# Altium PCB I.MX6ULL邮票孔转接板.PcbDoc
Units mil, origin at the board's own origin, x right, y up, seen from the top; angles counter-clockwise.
Board outline 1815 x 1660 mil, 2 copper layers (Top Layer, Bottom Layer); 3 components, 118 nets, 240 pads, 181 vias.
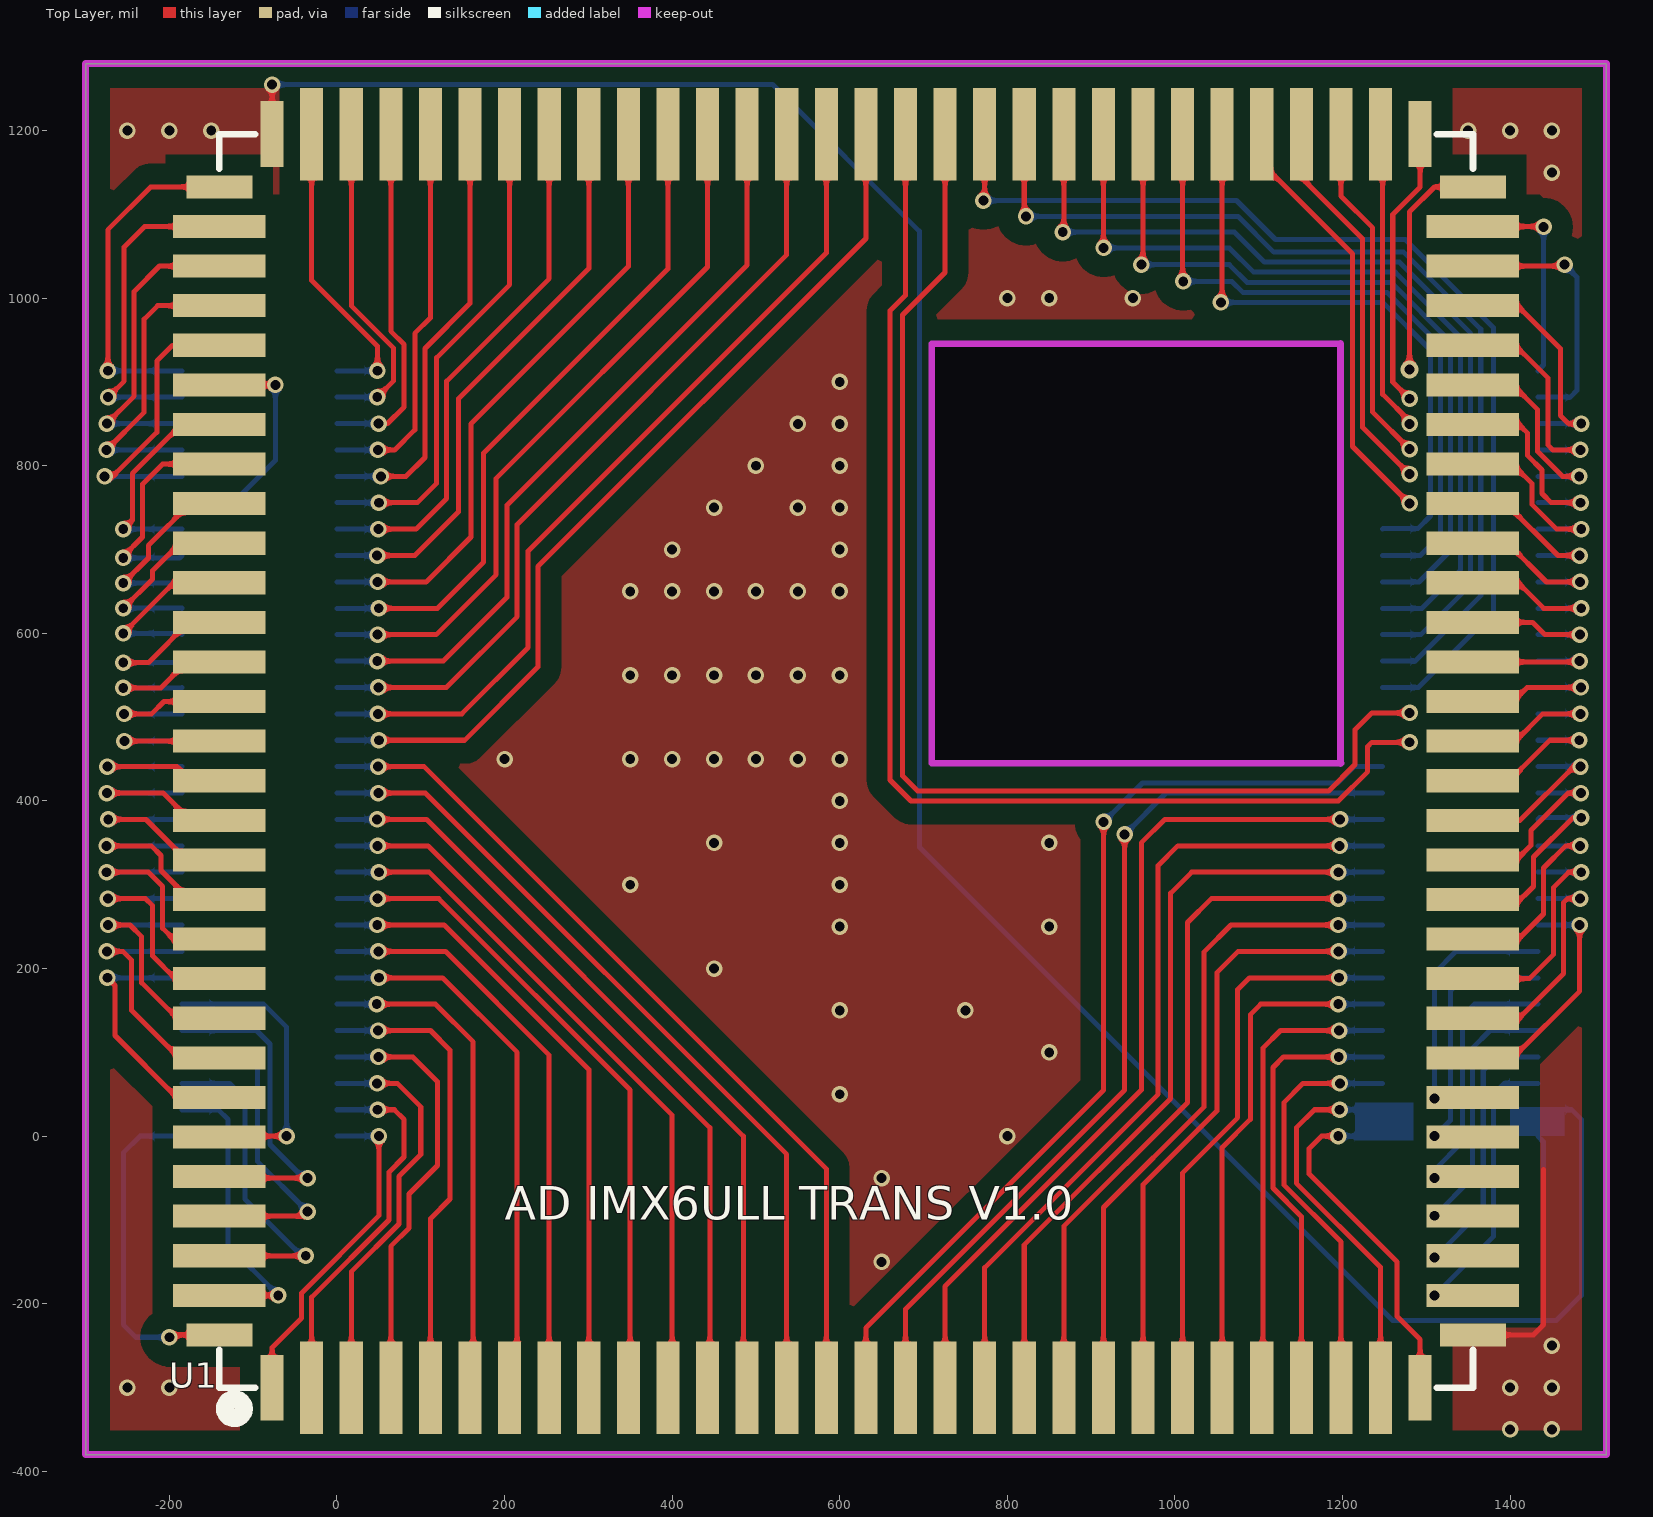
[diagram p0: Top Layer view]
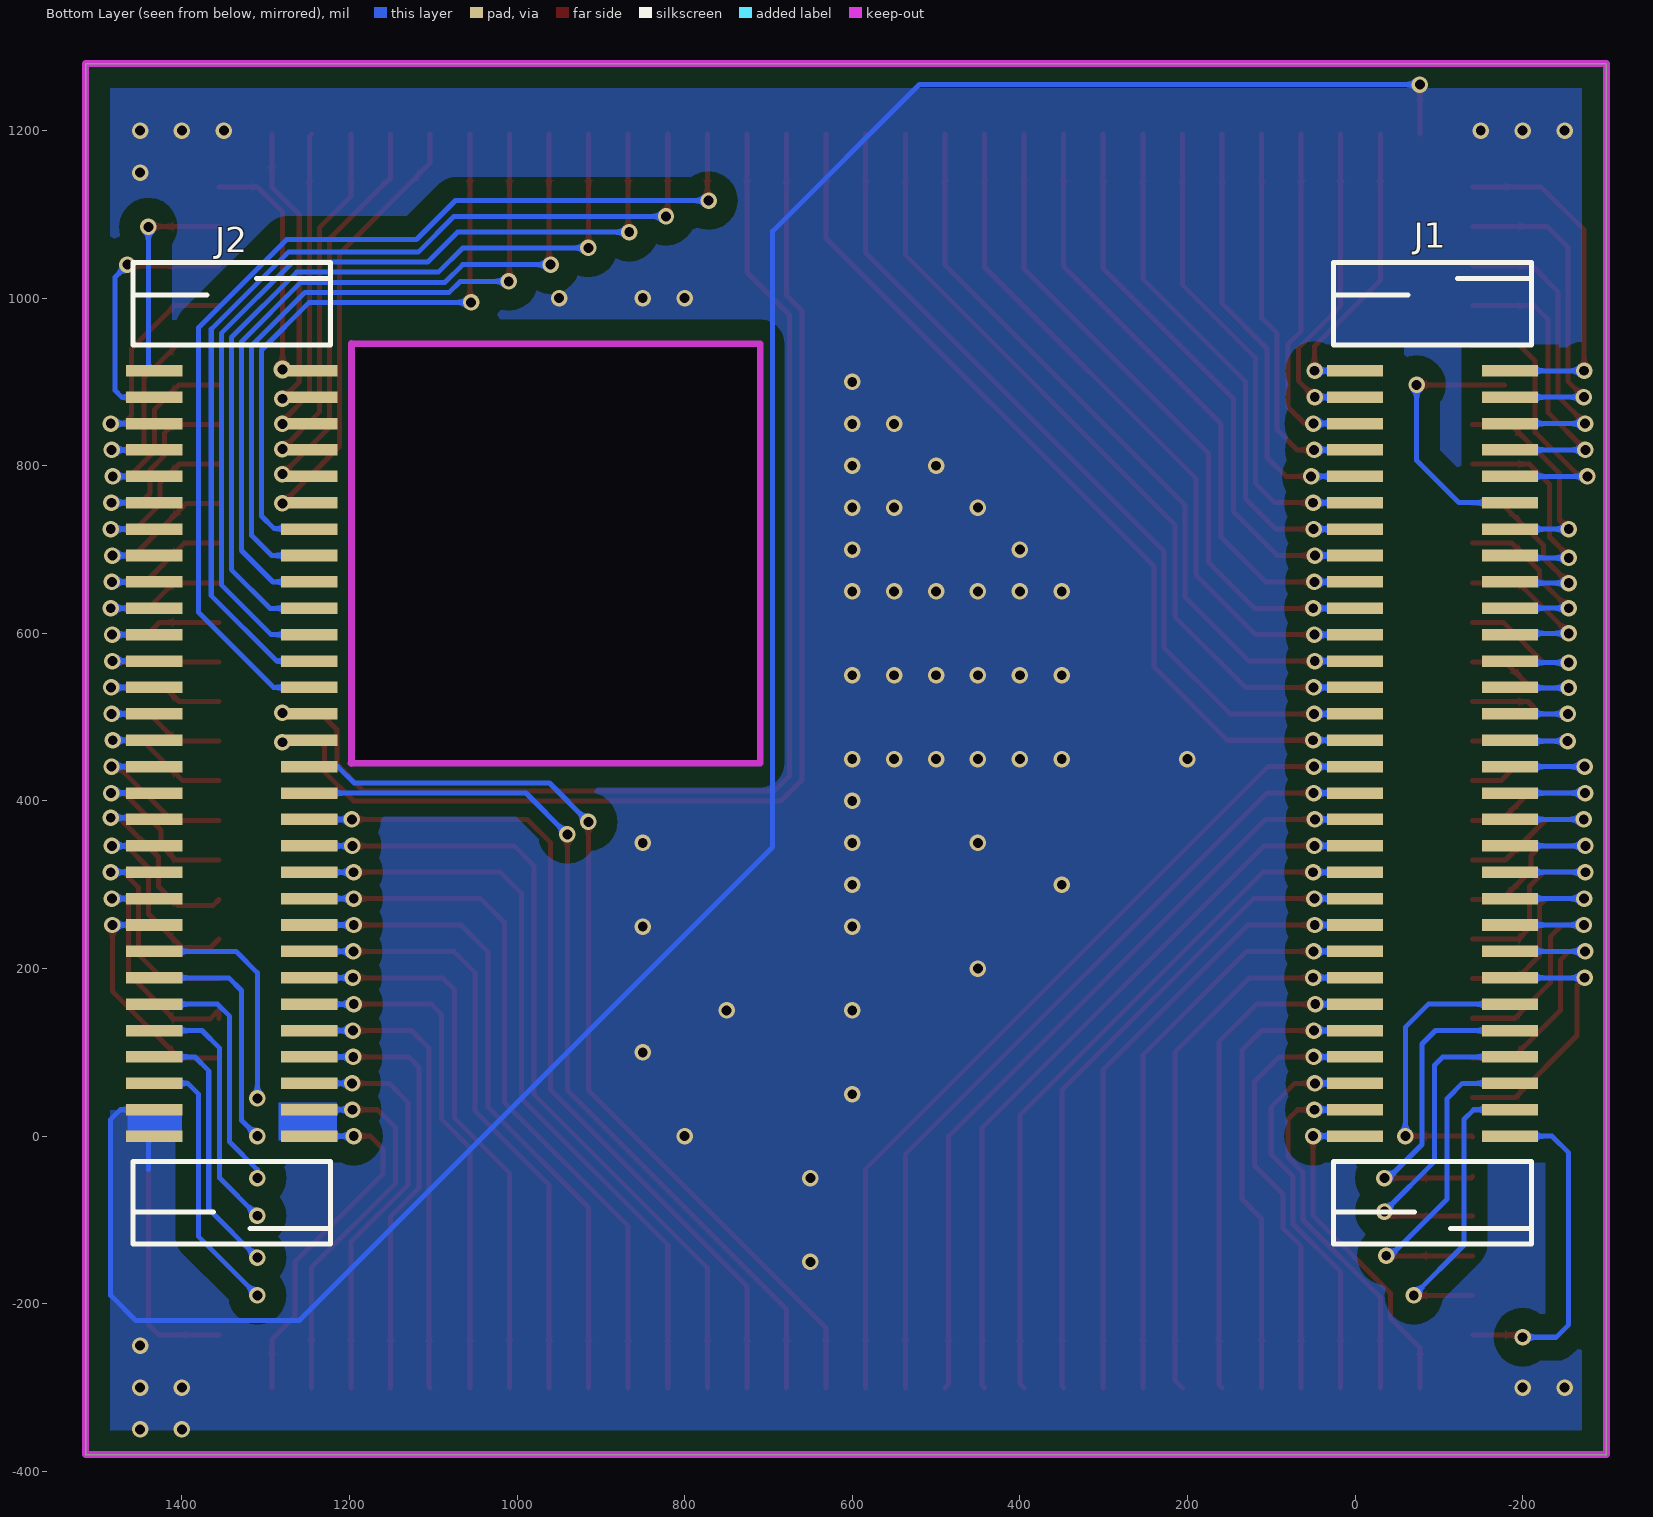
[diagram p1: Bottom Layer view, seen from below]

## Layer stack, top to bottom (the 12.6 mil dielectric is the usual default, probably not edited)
Top Solder: solder mask 0.4, Solder Resist, Dk 3.5
Top Layer: signal copper 1.4
Dielectric 1: dielectric 12.6, FR-4, Dk 4.8
Bottom Layer: signal copper 1.4
Bottom Solder: solder mask 0.4, Solder Resist, Dk 3.5

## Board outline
-300,-380 -300,1280 1515,1280 1515,-380
cut-out: 710,445 710,945.79 1197.6,945.98 1197.6,444.72 1198.19,445

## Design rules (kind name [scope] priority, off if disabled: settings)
Clearance [All] p1: gap=6
ComponentClearance [All] p1 off: gap=10 collisioncheckmode=3 verticalgap=10 showdistances=FALSE
HoleToHoleClearance [All] p1 off: gap=10 allowstackedmicrovias=TRUE
MinimumSolderMaskSliver [All] p1 off: minsoldermaskwidth=10
PlaneClearance [All] p1: clearance=10
PlaneConnect [All] p1: planeconnectstyle=Direct reliefexpansion=20 reliefentries=4 reliefconductorwidth=10 reliefairgap=10
PolygonConnect [All] p1: connectstyle=Direct reliefconductorwidth=10 reliefentries=4 polygonreliefangle="90 Angle" airgapwidth=10
RoutingVias [All] p1: holewidth=28 width=50 viastyle="Through Hole" minholewidth=10 minwidth=11 maxholewidth=900 maxwidth=1000
SilkToSilkClearance [All] p1 off: silktosilkclearance=10
SilkToSolderMaskClearance [IsPad] p1 off: minsilkscreentomaskgap=10 clearancetoexposedcopper=TRUE
SolderMaskExpansion [All] p1: expansion=4
Width [All] p1: maxlimit=1000 minlimit=1 preferedwidth=10
23 further rules are at their usual default settings.

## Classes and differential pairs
component class I.MX6ULL邮票孔转接板: J1 J2

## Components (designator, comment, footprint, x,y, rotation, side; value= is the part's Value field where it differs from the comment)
J1 "3710M060046G3FT01" 3710F060046G3FT01 0,0 r0 bottom locked
J2 "3710M060046G3FT01" 3710F060046G3FT01 1433.07,0 r0 bottom locked
U1 "ATKIMX6ULLCORE-S" ATKIMX6ULLCORE-S -77.4,-300.28 r90 top

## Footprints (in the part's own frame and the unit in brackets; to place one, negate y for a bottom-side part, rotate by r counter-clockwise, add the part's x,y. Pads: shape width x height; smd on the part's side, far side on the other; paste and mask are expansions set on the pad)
3710F060046G3FT01 [mm]
  rect 1.7x0.35 smd: 1(-4.7,0) 2(-4.7,-0.8) 3(-4.7,-1.6) 4(-4.7,-2.4) 5(-4.7,-3.2) 6(-4.7,-4) 7(-4.7,-4.8) 8(-4.7,-5.6) 9(-4.7,-6.4) 10(-4.7,-7.2) 11(-4.7,-8) 12(-4.7,-8.8) 13(-4.7,-9.6) 14(-4.7,-10.4) 15(-4.7,-11.2) 16(-4.7,-12) 17(-4.7,-12.8) 18(-4.7,-13.6) 19(-4.7,-14.4) 20(-4.7,-15.2) 21(-4.7,-16) 22(-4.7,-16.8) 23(-4.7,-17.6) 24(-4.7,-18.4) 25(-4.7,-19.2) 26(-4.7,-20) 27(-4.7,-20.8) 28(-4.7,-21.6) 29(-4.7,-22.4) 30(-4.7,-23.2) 31(0,-23.2) 32(0,-22.4) 33(0,-21.6) 34(0,-20.8) 35(0,-20) 36(0,-19.2) 37(0,-18.4) 38(0,-17.6) 39(0,-16.8) 40(0,-16) 41(0,-15.2) 42(0,-14.4) 43(0,-13.6) 44(0,-12.8) 45(0,-12) 46(0,-11.2) 47(0,-10.4) 48(0,-9.6) 49(0,-8.8) 50(0,-8) 51(0,-7.2) 52(0,-6.4) 53(0,-5.6) 54(0,-4.8) 55(0,-4) 56(0,-3.2) 57(0,-2.4) 58(0,-1.6) 59(0,-0.8) 60(0,0)
  silkscreen extent -5.35,-26.47 0.65,3.27
ATKIMX6ULLCORE-S [mm] "正点原子I.MX6ULL邮票孔核心板"
  rect 2x0.7 smd: 1(0,0) 30(0,-34.8) 61(38,-34.8) 90(38,0)
  rect 2.8x0.7 smd: 2(0,-1.2) 3(0,-2.4) 4(0,-3.6) 5(0,-4.8) 6(0,-6) 7(0,-7.2) 8(0,-8.4) 9(0,-9.6) 10(0,-10.8) 11(0,-12) 12(0,-13.2) 13(0,-14.4) 14(0,-15.6) 15(0,-16.8) 16(0,-18) 17(0,-19.2) 18(0,-20.4) 19(0,-21.6) 20(0,-22.8) 21(0,-24) 22(0,-25.2) 23(0,-26.4) 24(0,-27.6) 25(0,-28.8) 26(0,-30) 27(0,-31.2) 28(0,-32.4) 29(0,-33.6) 62(38,-33.6) 63(38,-32.4) 64(38,-31.2) 65(38,-30) 66(38,-28.8) 67(38,-27.6) 68(38,-26.4) 69(38,-25.2) 70(38,-24) 71(38,-22.8) 72(38,-21.6) 73(38,-20.4) 74(38,-19.2) 75(38,-18) 76(38,-16.8) 77(38,-15.6) 78(38,-14.4) 79(38,-13.2) 80(38,-12) 81(38,-10.8) 82(38,-9.6) 83(38,-8.4) 84(38,-7.2) 85(38,-6) 86(38,-4.8) 87(38,-3.6) 88(38,-2.4) 89(38,-1.2)
  rect 0.7x2 smd: 31(1.6,-36.4) 60(36.4,-36.4) 91(36.4,1.6) 120(1.6,1.6)
  rect 0.7x2.8 smd: 32(2.8,-36.4) 33(4,-36.4) 34(5.2,-36.4) 35(6.4,-36.4) 36(7.6,-36.4) 37(8.8,-36.4) 38(10,-36.4) 39(11.2,-36.4) 40(12.4,-36.4) 41(13.6,-36.4) 42(14.8,-36.4) 43(16,-36.4) 44(17.2,-36.4) 45(18.4,-36.4) 46(19.6,-36.4) 47(20.8,-36.4) 48(22,-36.4) 49(23.2,-36.4) 50(24.4,-36.4) 51(25.6,-36.4) 52(26.8,-36.4) 53(28,-36.4) 54(29.2,-36.4) 55(30.4,-36.4) 56(31.6,-36.4) 57(32.8,-36.4) 58(34,-36.4) 59(35.2,-36.4) 92(35.2,1.6) 93(34,1.6) 94(32.8,1.6) 95(31.6,1.6) 96(30.4,1.6) 97(29.2,1.6) 98(28,1.6) 99(26.8,1.6) 100(25.6,1.6) 101(24.4,1.6) 102(23.2,1.6) 103(22,1.6) 104(20.8,1.6) 105(19.6,1.6) 106(18.4,1.6) 107(17.2,1.6) 108(16,1.6) 109(14.8,1.6) 110(13.6,1.6) 111(12.4,1.6) 112(11.2,1.6) 113(10,1.6) 114(8.8,1.6) 115(7.6,1.6) 116(6.4,1.6) 117(5.2,1.6) 118(4,1.6) 119(2.8,1.6)
  Keep-Out Layer lines w0.203: 18.923,-32.385 31.65,-32.385 ; 31.655,-32.385 31.65,-20 18.93,-20 18.93,-32.4
  silkscreen extent -0.92,-36.4 38,1.6

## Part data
J1 J2: library part 3710F, "3710F060046G3FT01"
U1: "正点原子I.MX6ULL邮票孔核心板"

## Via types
v1: diameter 19.68, hole 11.81, Top Layer to Bottom Layer, 180 vias
v2: diameter 21.65, hole 11.81, Top Layer to Bottom Layer, 1 vias

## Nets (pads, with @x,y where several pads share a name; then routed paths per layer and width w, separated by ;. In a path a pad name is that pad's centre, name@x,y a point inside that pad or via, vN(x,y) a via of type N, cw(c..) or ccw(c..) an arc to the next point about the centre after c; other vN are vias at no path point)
6D_INT: J2.22 U1.68 | length 909.3
  Top Layer w6: v1(960,1040) 961.97,1041.97 U1.68
  Bottom Layer w6: v1(960,1040) 1065,1040 1086,1019 1258.12,1019 1329,948.12 1329,699 1291.42,661.42 J2.22
AP_INT: J2.49 U1.41 | length 265.1
  Top Layer w6: U1.41 1365.83,225 1400,225 1440,265 1440,320 1466.46,346.46 v1(1483.54,346.46)
  Bottom Layer w6: J2.49 v1(1483.54,346.46)
AUD_INT: J2.3 U1.28 | length 496.1
  Top Layer w6: v1(1197.01,62.99) 1152.99,62.99 1130,40 1130,-58.03 1198.19,-126.22 U1.28
  Bottom Layer w6: v1(1197.01,62.99) J2.3
BEEP: J2.5 U1.26 | length 557.5
  Top Layer w6: U1.26 1105,-298.98 1105,105 1125.98,125.98 v1(1195.98,125.98)
  Bottom Layer w6: v1(1195.98,125.98) J2.5
BLT_PWM: J2.16 U1.74 | length 1455.4
  Top Layer w6: U1.74 678.5,1003.5 660,985 660,425 685,400 1195,400 1230,435 1230,465 1235,470 v1(1280,470)
BOOT_MODE0: J2.7 U1.24 | length 681.3
  Top Layer w6: U1.24 1009.21,-43.82 1075,21.97 1075,175 1088.98,188.98 v1(1196.02,188.98)
  Bottom Layer w6: v1(1196.02,188.98) J2.7
BOOT_MODE1: J2.8 U1.23 | length 740.3
  Top Layer w6: U1.23 961.97,-58.03 1050,30 1050,195 1075.47,220.47 v1(1195.47,220.47)
  Bottom Layer w6: v1(1195.47,220.47) J2.8
CAN1_RX: J2.35 U1.55 | length 251
  Top Layer w6: U1.55 1403.43,896.57 1433,867 1433,817 1462.6,787.4 v1(1482.6,787.4)
  Bottom Layer w6: J2.35 v1(1482.6,787.4)
CAN1_TX: J2.36 U1.54 | length 250.4
  Top Layer w6: U1.54 1410.67,849.33 1421,839 1421,812.03 1438,795.03 1438,767 1449.09,755.91 v1(1484.09,755.91)
  Bottom Layer w6: J2.36 v1(1484.09,755.91)
CSI_DATA0: J1.56 U1.5 | length 557.2
  Top Layer w6: v1(49.02,125.98) 111.57,125.98 135,102.56 135,-75 111.57,-98.43 U1.5
  Bottom Layer w6: J1.56 v1(49.02,125.98)
CSI_DATA1: J1.57 U1.4 | length 520.5
  Top Layer w6: v1(49.49,94.49) 90.51,94.49 120,65 120,-35 86,-69 86,-109.91 64.33,-131.58 U1.4
  Bottom Layer w6: J1.57 v1(49.49,94.49)
CSI_DATA2: J1.3 U1.118 | length 406.6
  Top Layer w6: U1.118 v1(-37.2,-142.8)
  Bottom Layer w6: J1.3 -127.99,62.99 -110,45 -110,-75 -42.2,-142.8 v1(-37.2,-142.8)
CSI_DATA3: J1.59 U1.2 | length 450.7
  Top Layer w6: U1.2 -30.16,-192.13 62,-99.97 62,-43 80,-25 80,20 68.5,31.5 v1(48.5,31.5)
  Bottom Layer w6: J1.59 v1(48.5,31.5)
CSI_DATA4: J1.55 U1.6 | length 595.4
  Top Layer w6: v1(47.52,157.48) 117.52,157.48 162.52,112.48 162.52,-296.57 U1.6
  Bottom Layer w6: J1.55 v1(47.52,157.48)
CSI_DATA5: J1.6 U1.115 | length 347.3
  Top Layer w6: U1.115 -139.33,0 v1(-60,0)
  Bottom Layer w6: J1.6 -87.48,157.48 -60,130 v1(-60,0)
CSI_DATA6: J1.4 U1.117 | length 398
  Top Layer w6: U1.117 -40.55,-95.55 v1(-35,-90)
  Bottom Layer w6: J1.4 -104.49,94.49 -95,85 -95,-30 v1@-37.5,-87.5
CSI_DATA7: J1.58 U1.3 | length 481.2
  Top Layer w6: U1.3 17.09,-161.85 74,-104.94 74,-47.97 100,-21.97 100,35 72.01,62.99 v1(47.99,62.99)
  Bottom Layer w6: J1.58 v1(47.99,62.99)
CSI_HSYNC: J1.1 U1.120 | length 405.2
  Top Layer w6: v1(-200,-240) -197.28,-237.28 U1.120
  Bottom Layer w6: v1(-200,-240) -240,-240 -255,-225 -255,-20 -235,0 J1.1
CSI_MCLK: J1.2 U1.119 | length 365.1
  Top Layer w6: U1.119 v1(-70,-190.04)
  Bottom Layer w6: J1.2 -141.5,31.5 -130,20 -130,-130 v1(-70,-190.04)
CSI_PIXCLK: J1.5 U1.116 | length 399.3
  Top Layer w6: U1.116 -138.7,-50 v1(-35,-50)
  Bottom Layer w6: J1.5 -95.98,125.98 -80,110 -80,-10 -40,-50 v1(-35,-50)
CSI_PWDN: J2.14 U1.17 | length 1097.1
  Top Layer w6: U1.17 678.5,-206.5 940,55 v1(940,360)
  Bottom Layer w6: v1(940,360) 989.45,409.45 J2.14
CSI_RESET: J2.13 U1.18 | length 1051.2
  Top Layer w6: U1.18 725.75,-179.25 960,55 960,350 987.95,377.95 v1(1197.05,377.95) v1@1197.05,373.69
  Bottom Layer w6: v1(1197.05,377.95) J2.13
CSI_VSYNC: J1.60 U1.1 | length 403
  Top Layer w6: U1.1 -77.4,-252.4 -42.16,-217.16 -42.16,-187.16 50,-95 v1(50,0)
  Bottom Layer w6: J1.60 v1(50,0)
CT_INT: J2.15 U1.16 | length 1153.2
  Top Layer w6: U1.16 631.26,-228.74 915,55 v1(915,375)
  Bottom Layer w6: v1(915,375) 961.45,421.45 1194.48,421.45 1213.97,440.94 J2.15
CT_RST: J1.48 U1.13 | length 943.7
  Top Layer w6: v1(47.95,377.95) 107.05,377.95 485,0 485,-295.75 U1.13
  Bottom Layer w6: J1.48 v1(47.95,377.95)
DC5V: J2.1 J2.2 U1.29 U1.30 | length 898.3
  Top Layer w6: v1(1195,0) 1175,0 1160,-15 1160,-45 1265,-150 1265,-215 1292.68,-242.68 U1.30 ; v1(1196.5,31.5) 1166.5,31.5 1145,10 1145,-56.06 1245.43,-156.49 U1.29
  Bottom Layer w6: v1(1195,0) J2.1 ; v1(1196.5,31.5) J2.2
ECSPI3_MISO: J2.40 U1.50 | length 193.9
  Top Layer w6: U1.50 1409.65,660.35 1440.08,629.92 v1(1485,629.92)
  Bottom Layer w6: J2.40 v1(1485,629.92)
ECSPI3_MOSI: J2.39 U1.51 | length 197.6
  Top Layer w6: U1.51 1397.4,707.6 1443.58,661.42 v1(1483.58,661.42)
  Bottom Layer w6: J2.39 v1(1483.58,661.42)
ECSPI3_SCLK: J2.41 U1.49 | length 184.2
  Top Layer w6: U1.49 1426.89,613.11 1441.57,598.43 v1(1483.43,598.43)
  Bottom Layer w6: J2.41 v1(1483.43,598.43)
ECSPI3_SS0: J2.42 U1.48 | length 177.8
  Top Layer w6: U1.48 1482.01,565.87 v1(1483.07,566.93)
  Bottom Layer w6: J2.42 v1(1483.07,566.93)
ENET1_CRS_DV: J2.25 U1.65 | length 513.8
  Top Layer w6: U1.65 1103.7,1161.3 1212,1053 1212,823 v1(1280,755)
ENET1_INT: J2.11 U1.20 | length 926
  Top Layer w6: U1.20 820.24,-129.76 995,45 995,290 1019.96,314.96 v1(1195.04,314.96)
  Bottom Layer w6: v1(1195.04,314.96) J2.11
ENET1_RST: J2.10 U1.21 | length 861.2
  Top Layer w6: U1.21 867.48,-107.52 1015,40 1015,255 1043.46,283.46 v1(1195,283.46)
  Bottom Layer w6: v1(1195,283.46) J2.10
ENET1_RXD0: J2.26 U1.64 | length 459.2
  Top Layer w6: U1.64 1150.94,1144.06 1224,1071 1224,846 v1(1280,790)
ENET1_RXD1: J2.24 U1.66 | length 736.5
  Top Layer w6: v1(1055,995) 1056.46,996.46 U1.66
  Bottom Layer w6: v1(1055,995) 1248.18,995 1305,938.18 1305,740 1290,725 1248.62,725 J2.24
ENET1_RXER: J2.30 U1.60 | length 276
  Top Layer w6: v2(1280,915) 1280,1103.03 1309.77,1132.8 U1.60
ENET1_TX_CLK: J2.29 U1.61 | length 337.6
  Top Layer w6: v1(1280,880) 1260,900 1260,1100 1292.68,1132.68 U1.61
ENET1_TXD0: J2.23 U1.67 | length 820
  Top Layer w6: U1.67 1009.21,1020.79 v1(1010,1020)
  Bottom Layer w6: v1(1010,1020) 1068.03,1020 1081.03,1007 1253.15,1007 1317,943.15 1317,717 1292.91,692.91 J2.23
ENET1_TXD1: J2.28 U1.62 | length 360.1
  Top Layer w6: U1.62 1248,1193.22 1248,885.35 1280,853.35 v1(1280,850)
ENET1_TXEN: J2.27 U1.63 | length 409.7
  Top Layer w6: U1.63 1198.19,1121.81 1236,1084 1236,864 v1(1280,820)
ENET2_CRS_DV: J1.33 U1.87 | length 420.4
  Top Layer w6: v1(49.61,850.39) 60.39,850.39 80,870 80,945 64.33,960.67 U1.87
  Bottom Layer w6: J1.33 v1(49.61,850.39)
ENET2_INT: J1.39 U1.81 | length 740.8
  Top Layer w6: v1(48.58,661.42) 106.42,661.42 160,715 160,850 347.8,1037.8 U1.81
  Bottom Layer w6: J1.39 v1(48.58,661.42)
ENET2_RST: J2.9 U1.22 | length 796.4
  Top Layer w6: U1.22 914.72,-85.28 1035,35 1035,220 1066.97,251.97 v1(1195,251.97)
  Bottom Layer w6: v1(1195,251.97) J2.9
ENET2_RXD0: J1.38 U1.82 | length 681.8
  Top Layer w6: v1(47.91,692.91) 92.91,692.91 145,745 145,880 300.55,1035.55 U1.82
  Bottom Layer w6: J1.38 v1(47.91,692.91)
ENET2_RXD1: J1.37 U1.83 | length 631.6
  Top Layer w6: v1(49.41,724.41) 94.41,724.41 131,761 131,901 253.31,1023.31 U1.83
  Bottom Layer w6: J1.37 v1(49.41,724.41)
ENET2_RXER: J1.34 U1.86 | length 463.5
  Top Layer w6: v1(48.9,818.9) 68.9,818.9 93,843 93,958 111.57,976.57 U1.86
  Bottom Layer w6: J1.34 v1(48.9,818.9)
ENET2_TX_CLK: J1.31 U1.89 | length 363.3
  Top Layer w6: U1.89 -30.16,1021.22 48.39,942.67 v1(48.39,913.39)
  Bottom Layer w6: J1.31 v1(48.39,913.39)
ENET2_TXD0: J1.36 U1.84 | length 581.4
  Top Layer w6: v1(50,755.91) 95.91,755.91 119,779 119,929 206.06,1016.06 U1.84
  Bottom Layer w6: J1.36 v1(50,755.91)
ENET2_TXD1: J1.35 U1.85 | length 522.4
  Top Layer w6: v1(52.4,787.4) 82.4,787.4 105,810 105,940 158.82,993.82 U1.85
  Bottom Layer w6: J1.35 v1(52.4,787.4)
ENET2_TXEN: J1.32 U1.88 | length 390.7
  Top Layer w6: U1.88 17.09,990.94 67.23,940.8 67.23,901.01 v1(48.11,881.89)
  Bottom Layer w6: J1.32 v1(48.11,881.89)
GND: J2.59 J2.60 U1.31 U1.90 | length 3259.5
  Top Layer w6: U1.90 v1(-77.4,1255) ; U1.31 1427.72,-237.28 1440,-225 1440,-40
  Bottom Layer w6: v1(-77.4,1255) 520,1255 695,1080 695,345 1260,-220 1455,-220 1485,-190 1485,20 1473.5,31.5 J2.59 ; J2.60 1440,-6.93 1440,-40
  other v1: 1400,-350 1450,-350 -250,-300 -200,-300 1400,-300 1450,-300 1450,-250 650,-150 650,-50 800,0 600,50 850,100 600,150 750,150 450,200 600,250 850,250 350,300 600,300 450,350 600,350 850,350 600,400 200,450 350,450 400,450 450,450 500,450 550,450 600,450 350,550 400,550 450,550 500,550 550,550 600,550 350,650 400,650 450,650 500,650 550,650 600,650 400,700 600,700 450,750 550,750 600,750 500,800 600,800 550,850 600,850 600,900 800,1000 850,1000 950,1000 1450,1150 -250,1200 -200,1200 -150,1200 1350,1200 1400,1200 1450,1200
GPIO_0: J2.51 U1.39 | length 301.8
  Top Layer w6: U1.39 1355.67,150.67 1366.34,140 1410,140 1464,194 1464,279 1468.46,283.46 v1(1483.46,283.46)
  Bottom Layer w6: J2.51 v1(1483.46,283.46)
GPIO_3: J2.47 U1.43 | length 223.8
  Top Layer w6: U1.43 1407.68,329.65 1425,346.97 1425,365 1469.45,409.45 v1(1484.45,409.45)
  Bottom Layer w6: J2.47 v1(1484.45,409.45)
GPIO_5: J1.47 U1.14 | length 993.9
  Top Layer w6: v1(49.45,409.45) 105.55,409.45 536.77,-21.77 U1.14
  Bottom Layer w6: J1.47 v1(49.45,409.45)
GPIO_6: J2.44 U1.46 | length 192.6
  Top Layer w6: U1.46 1406.38,471.38 1438.94,503.94 v1(1483.94,503.94)
  Bottom Layer w6: J2.44 v1(1483.94,503.94)
GPIO_7: J2.45 U1.45 | length 196.4
  Top Layer w6: U1.45 1399.13,424.13 1447.44,472.44 v1(1482.56,472.44)
  Bottom Layer w6: J2.45 v1(1482.56,472.44)
I2C1_SCL: J2.33 U1.57 | length 286.4
  Top Layer w6: U1.57 1408.94,991.06 1460,940 1460,860 1469.61,850.39 v1(1485,850.39)
  Bottom Layer w6: J2.33 v1(1485,850.39)
I2C1_SDA: J2.34 U1.56 | length 277.7
  Top Layer w6: U1.56 1406.18,943.82 1445,905 1445,825 1451.1,818.9 v1(1483.9,818.9)
  Bottom Layer w6: J2.34 v1(1483.9,818.9)
I2C2_SCL: J2.31 U1.59 | length 259
  Top Layer w6: U1.59 1439.45,1085.55 v1(1440,1085)
  Bottom Layer w6: J2.31 1440,920.31 v1(1440,1085)
I2C2_SDA: J2.32 U1.58 | length 316.5
  Top Layer w6: U1.58 1463.31,1038.31 v1(1465,1040)
  Bottom Layer w6: J2.32 1471.89,881.89 1480,890 1480,1025 v1(1465,1040)
JTAG_NTRST: J2.21 U1.69 | length 995.3
  Top Layer w6: U1.69 914.72,1060.28 v1(915,1060)
  Bottom Layer w6: v1(915,1060) 1065,1060 1094,1031 1263.09,1031 1341,953.09 1341,676 1294.92,629.92 J2.21
JTAG_TCK: J2.19 U1.71 | length 1164.8
  Top Layer w6: U1.71 820.24,1099.76 v1(822.32,1097.69)
  Bottom Layer w6: v1(822.32,1097.69) 1075.34,1097.69 1118.03,1055 1273.03,1055 1365,963.03 1365,645 1286.93,566.93 J2.19
JTAG_TDI: J2.17 U1.73 | length 1462.1
  Top Layer w6: U1.73 725.75,1030.75 675,980 675,430 693,412 1183.57,412 1215,443.43 1215,485 1235,505 v1(1280,505)
JTAG_TDO: J2.18 U1.72 | length 1260.2
  Top Layer w6: v1(771.53,1116.53) 772.99,1117.99 U1.72
  Bottom Layer w6: v1(771.53,1116.53) 1073.47,1116.53 1120,1070 1275,1070 1380,965 1380,625 1290.43,535.43 J2.18
JTAG_TMS: J2.20 U1.70 | length 1084.1
  Top Layer w6: v1(866.16,1078.84) 867.48,1080.17 U1.70
  Bottom Layer w6: v1(866.16,1078.84) 1071.16,1078.84 1107,1043 1268.06,1043 1353,958.06 1353,658 1293.43,598.43 J2.20
KEY0: J2.48 U1.42 | length 249.2
  Top Layer w6: U1.42 1363.07,275 1405,275 1428,298 1428,333 1475,380 v1(1485,380)
  Bottom Layer w6: J2.48 1435.12,380 v1(1485,380)
LCD_DATA0: J1.7 U1.114 | length 316.8
  Top Layer w6: v1(-273.98,188.98) -265,180 -265,120 -191.18,46.18 U1.114
  Bottom Layer w6: v1(-273.98,188.98) J1.7
LCD_DATA1: J1.8 U1.113 | length 311.4
  Top Layer w6: v1(-274.53,220.47) -255.47,220.47 -245,210 -245,150 -188.43,93.43 U1.113
  Bottom Layer w6: v1(-274.53,220.47) J1.8
LCD_DATA2: J1.9 U1.112 | length 298.9
  Top Layer w6: v1(-273.03,251.97) -246.97,251.97 -233,238 -233,183 -190.67,140.67 U1.112
  Bottom Layer w6: v1(-273.03,251.97) J1.9
LCD_DATA3: J1.10 U1.111 | length 296.2
  Top Layer w6: v1(-273.46,283.46) -228.46,283.46 -220,275 -220,215 -192.91,187.91 U1.111
  Bottom Layer w6: v1(-273.46,283.46) J1.10
LCD_DATA4: J1.11 U1.110 | length 286.8
  Top Layer w6: v1(-274.96,314.96) -224.96,314.96 -208,298 -208,248 -195.16,235.16 U1.110
  Bottom Layer w6: v1(-274.96,314.96) J1.11
LCD_DATA5: J1.12 U1.109 | length 261.7
  Top Layer w6: v1(-275,346.46) -221.46,346.46 -210,335 -210,316.97 -175.43,282.4 U1.109
  Bottom Layer w6: v1(-275,346.46) J1.12
LCD_DATA6: J1.13 U1.108 | length 240.5
  Top Layer w6: v1(-272.95,377.95) -227.95,377.95 -179.65,329.65 U1.108
  Bottom Layer w6: v1(-272.95,377.95) J1.13
LCD_DATA7: J1.14 U1.107 | length 237
  Top Layer w6: v1(-274.45,409.45) -274.39,409.51 -207.4,409.51 -174.78,376.89 U1.107
  Bottom Layer w6: v1(-274.45,409.45) J1.14
LCD_DATA8: J1.15 U1.106 | length 229.6
  Top Layer w6: v1(-274.06,440.94) -190.94,440.94 -174.13,424.13 U1.106
  Bottom Layer w6: v1(-274.06,440.94) J1.15
LCD_DATA9: J1.16 U1.105 | length 182.3
  Top Layer w6: v1(-253.62,471.38) U1.105
  Bottom Layer w6: v1(-253.62,471.38) -186.1,471.38 J1.16
LCD_DATA10: J1.17 U1.104 | length 190
  Top Layer w6: v1(-253.94,503.94) -221.06,503.94 -206.38,518.62 U1.104
  Bottom Layer w6: v1(-253.94,503.94) J1.17 J1.17@-186.1,505
LCD_DATA11: J1.18 U1.103 | length 197.5
  Top Layer w6: v1(-255,535) -210,535 -179.13,565.87 U1.103
  Bottom Layer w6: v1(-255,535) -185.47,535 J1.18
LCD_DATA12: J1.19 U1.102 | length 205.3
  Top Layer w6: v1(-255,565) -225,565 -176.89,613.11 U1.102
  Bottom Layer w6: v1(-255,565) -186.97,565 J1.19
LCD_DATA13: J1.20 U1.101 | length 210.2
  Top Layer w6: v1(-255,600) -194.65,660.35 U1.101
  Bottom Layer w6: v1(-255,600) -186.61,600 J1.20
LCD_DATA14: J1.21 U1.100 | length 222.6
  Top Layer w6: v1(-255,630) -220,665 -220,675 -187.4,707.6 U1.100
  Bottom Layer w6: v1(-255,630) -185.12,630 J1.21
LCD_DATA15: J1.22 U1.99 | length 233.2
  Top Layer w6: v1(-255,660) -225,690 -225,705 -175.16,754.84 U1.99
  Bottom Layer w6: v1(-255,660) -186.46,660 J1.22
LCD_DATA16: J1.23 U1.98 | length 270.3
  Top Layer w6: v1(-255,690) -255,691.97 -232,714.97 -232,778 -207.91,802.09 U1.98
  Bottom Layer w6: v1(-255,690) -187.95,690 J1.23
LCD_DATA17: J1.24 U1.97 | length 268.9
  Top Layer w6: v1(-255,724.41) -244.16,735.25 -244.16,790.84 -185.67,849.33 U1.97
  Bottom Layer w6: v1(-255,724.41) J1.24
LCD_DATA18: J1.25 U1.96 | length 327.6
  Top Layer w6: U1.96@-178.43,896.57 U1.96 v1(-73.43,896.57)
  Bottom Layer w6: J1.25 -124.09,755.91 -73.43,806.57 v1(-73.43,896.57)
LCD_DATA19: J1.26 U1.95 | length 344
  Top Layer w6: v1(-277.4,787.4) -267.6,787.4 -215,840 -215,925 -196.18,943.82 U1.95
  Bottom Layer w6: v1(-277.4,787.4) J1.26
LCD_DATA20: J1.27 U1.94 | length 361
  Top Layer w6: v1(-275,818.9) -230,863.9 -230,975 -213.94,991.06 U1.94
  Bottom Layer w6: v1(-275,818.9) J1.27
LCD_DATA21: J1.28 U1.93 | length 374.8
  Top Layer w6: v1(-274.61,850.39) -242,883 -242,1008 -211.69,1038.31 U1.93
  Bottom Layer w6: v1(-274.61,850.39) J1.28
LCD_DATA22: J1.29 U1.92 | length 398.9
  Top Layer w6: v1(-273.11,881.89) -254,901 -254,1061 -229.45,1085.55 U1.92
  Bottom Layer w6: v1(-273.11,881.89) J1.29
LCD_DATA23: J1.30 U1.91 | length 410.8
  Top Layer w6: v1(-273.39,913.39) -273.39,1081.61 -222.2,1132.8 U1.91
  Bottom Layer w6: v1(-273.39,913.39) J1.30
LCD_DE: J1.46 U1.15 | length 1044.1
  Top Layer w6: v1(49.06,440.94) 104.06,440.94 584.02,-39.02 U1.15
  Bottom Layer w6: J1.46 v1(49.06,440.94)
LCD_HSYNC: J1.44 U1.76 | length 1021
  Top Layer w6: v1(48.94,503.94) 148.94,503.94 228,583 228,698 584.02,1054.02 U1.76
  Bottom Layer w6: J1.44 v1(48.94,503.94)
LCD_PCLK: J1.45 U1.75 | length 1074.1
  Top Layer w6: v1(50,472.44) 152.44,472.44 240,560 240,680 631.26,1071.26 U1.75
  Bottom Layer w6: J1.45 v1(50,472.44)
LCD_VSYNC: J1.43 U1.77 | length 959.1
  Top Layer w6: v1(49.57,535.43) 130.43,535.43 215,620 215,730 536.77,1051.77 U1.77
  Bottom Layer w6: J1.43 v1(49.57,535.43)
NUSB_OTG_CHD: J2.52 U1.38 | length 289.2
  Top Layer w6: U1.38 1403.43,93.43 1483.03,173.03 v1(1483.03,251.97)
  Bottom Layer w6: J2.52 v1(1483.03,251.97)
ONOFF: J2.4 U1.27 | length 532.5
  Top Layer w6: U1.27 1150.94,-95.94 1117,-62 1117,82 1129.49,94.49 v1(1195.51,94.49)
  Bottom Layer w6: v1(1195.51,94.49) J2.4
PMIC_ON_REQ: J1.41 U1.79 | length 849.9
  Top Layer w6: v1(48.43,598.43) 118.43,598.43 190,670 190,785 442.28,1037.28 U1.79
  Bottom Layer w6: J1.41 v1(48.43,598.43)
RESET: J1.40 U1.80 | length 799.7
  Top Layer w6: v1(49.92,629.92) 119.92,629.92 175,685 175,815 395.04,1035.04 U1.80
  Bottom Layer w6: J1.40 v1(49.92,629.92)
SD1_CLK: J1.54 U1.7 | length 655.8
  Top Layer w6: v1(50,188.98) 126.02,188.98 215,100 215,-291.34 U1.7
  Bottom Layer w6: J1.54 v1(50,188.98)
SD1_CMD: J1.53 U1.8 | length 701.5
  Top Layer w6: v1(49.53,220.47) 129.53,220.47 253.31,96.69 U1.8
  Bottom Layer w6: J1.53 v1(49.53,220.47)
SD1_DATA0: J1.49 U1.12 | length 895.8
  Top Layer w6: v1(48.54,346.46) 108.54,346.46 445,10 445,-297.56 U1.12
  Bottom Layer w6: J1.49 v1(48.54,346.46)
SD1_DATA1: J1.50 U1.11 | length 847.4
  Top Layer w6: v1(49.96,314.96) 110.04,314.96 400,25 400,-295.31 U1.11
  Bottom Layer w6: J1.50 v1(49.96,314.96)
SD1_DATA2: J1.52 U1.9 | length 751.7
  Top Layer w6: v1(48.03,251.97) 128.03,251.97 300.55,79.45 U1.9
  Bottom Layer w6: J1.52 v1(48.03,251.97)
SD1_DATA3: J1.51 U1.10 | length 800.8
  Top Layer w6: v1(48.46,283.46) 121.54,283.46 350,55 350,-298.07 U1.10
  Bottom Layer w6: J1.51 v1(48.46,283.46)
SNVS_TAMPER0: J2.6 U1.25 | length 622.4
  Top Layer w6: U1.25 1056.46,-13.54 1090,20 1090,145 1102.48,157.48 v1(1195,157.48)
  Bottom Layer w6: v1(1195,157.48) J2.6
SNVS_TAMPER2: J2.12 U1.19 | length 986.7
  Top Layer w6: U1.19 772.99,-157.01 980,50 980,322.91 1003.54,346.46 v1(1196.46,346.46)
  Bottom Layer w6: v1(1196.46,346.46) J2.12
UART1_RTS: J2.43 U1.47 | length 187.4
  Top Layer w6: U1.47 1403.62,518.62 1420.43,535.43 v1(1484.57,535.43)
  Bottom Layer w6: J2.43 v1(1484.57,535.43)
UART1_RXD: J2.46 U1.44 | length 205.9
  Top Layer w6: U1.44 1411.89,376.89 1475.94,440.94 v1(1484.06,440.94)
  Bottom Layer w6: J2.46 v1(1484.06,440.94)
UART1_TXD: J2.50 U1.40 | length 280.7
  Top Layer w6: U1.40 1422.91,187.91 1452,217 1452,297 1470,315 1484.92,315 v1(1484.96,314.96)
  Bottom Layer w6: J2.50 v1(1484.96,314.96)
UART3_RXD: J2.37 U1.53 | length 228.1
  Top Layer w6: U1.53 1402.91,802.09 1426,779 1426,754 1455.59,724.41 v1(1485,724.41)
  Bottom Layer w6: J2.37 v1(1485,724.41)
UART3_TXD: J2.38 U1.52 | length 202.7
  Top Layer w6: U1.52 1395.16,754.84 1457.09,692.91 v1(1482.91,692.91)
  Bottom Layer w6: J2.38 v1(1482.91,692.91)
USB_OTG1_DN: J2.53 U1.37 | length 283.6
  Bottom Layer w6: v1(1310,45) 1310,195 1335.47,220.47 J2.53
USB_OTG1_DP: J2.54 U1.36 | length 292.1
  Bottom Layer w6: v1(1310,0) 1328.84,18.84 1328.84,173.84 1343.98,188.98 J2.54
USB_OTG1_VBUS: J2.57 U1.33 | length 318.9
  Bottom Layer w6: v1(1310,-145) 1368,-87 1368,78 1384.49,94.49 J2.57
USB_OTG2_DN: J2.55 U1.35 | length 302.7
  Bottom Layer w6: v1(1310,-50) 1310,-40 1343,-7 1343,143 1357.48,157.48 J2.55
USB_OTG2_DP: J2.56 U1.34 | length 305.4
  Bottom Layer w6: v1(1310,-95) 1355,-50 1355,105 1375.98,125.98 J2.56
USB_OTG2_VBUS: J2.58 U1.32 | length 327.4
  Bottom Layer w6: v1(1310,-190) 1380,-120 1380,50 1392.99,62.99 J2.58
VDD_COIN_3V: J1.42 U1.78 | length 906
  Top Layer w6: v1(48.07,566.93) 126.93,566.93 203,643 203,753 489.53,1039.53 U1.78
  Bottom Layer w6: J1.42 v1(48.07,566.93)

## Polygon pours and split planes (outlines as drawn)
GND on Top Overlay "Mechanical 1-No Net" (solid, remove dead copper): -300,1280 1515,1280 1515,-380 -300,-380
GND on Bottom Layer "Mechanical 1-No Net" (solid, remove dead copper, pour order 4): -300,1280 1515,1280 1515,-380 -300,-380
GND on Top Layer "Mechanical 1-No Net" (solid, remove dead copper, pour order 6): -300,1280 1515,1280 1515,-380 -300,-380

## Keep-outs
Keep-Out Layer:
  the board outline again, w8

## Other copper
Bottom Layer:
  rectangle net DC5V: 1215,-5 1285,40
  rectangle net GND: 1400,0 1465,35

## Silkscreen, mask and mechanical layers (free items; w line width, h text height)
Top Overlay:
  text "AD IMX6ULL TRANS V1.0" at 200,-100 h40

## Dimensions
-300,1290 to 1515,1280 on Top Overlay
-300,1280 to -300,-380 on Top Overlay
